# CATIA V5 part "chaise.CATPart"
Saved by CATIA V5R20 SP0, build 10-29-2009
Part number: chese
Bounding box of the stored display mesh (mm): x -75.226 to 75.782, y -50 to 50, z -81 to 122
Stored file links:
  C:\Users\bensf\Desktop\bouthaina\chese.CATPart
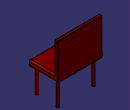
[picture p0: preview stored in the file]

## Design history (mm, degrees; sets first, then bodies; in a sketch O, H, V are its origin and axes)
Body1 (main body)
  Sketch1 on xy-plane, origin (0, 0, 0), H (1, 0, 0), V (0, 1, 0)
    line L1 (75.2257, 50) -> (75.2257, -50)
    line L2 (75.2257, -50) -> (-75.2257, -50)
    line L3 (-75.2257, -50) -> (-75.2257, 50)
    line L4 (-75.2257, 50) -> (75.2257, 50)
    length L3 = 100
    vertical: L1 V, L3 V
    horizontal: L2 H, L4 H
    equidistance: L1 L3 O, L2 L4 O
  Pad1: profile Sketch1, direction (0, 0, 1), length 20
  Sketch2 on end face of Pad1, origin (0, 0, 20), H (1, 0, 0), V (0, 1, 0)
    line L1 (75.7822, 40) -> (-74.2178, 40)
    line L2 (-74.2178, 40) -> (-74.2178, 50)
    line L3 (-74.2178, 50) -> (75.7822, 50)
    line L4 (75.7822, 50) -> (75.7822, 40)
    length L3 = 150
    horizontal: L1 H, L3 H
    vertical: L2 V, L4 V
  Pad2: profile Sketch2, direction (0, 0, 1), length 102
  Sketch3 on start face of Pad1, origin (0, 0, 0), H (1, 0, 0), V (0, -1, 0)
    circle A1 centre (60.3966, 35.0158) radius 5
    circle A2 centre (-60.3966, 35.0158) radius 5
    circle A3 centre (60.3966, -35.0158) radius 5
    circle A4 centre (-60.3966, -35.0158) radius 5
    radius A1 = 5
    symmetry: A1 A2 V, A1 A3 H, A2 A4 H
  Pad3: profile Sketch3, direction (0, 0, -1), length 81
  Fillet1: radius 5, on edge [face of Pad1 from Sketch1.L1 | end face of Pad1]
  Fillet2: radius 5, on edge [face of Pad1 from Sketch1.L2 | end face of Pad1]
  Fillet3: radius 5, on edge [face of Pad1 from Sketch1.L3 | end face of Pad1]
  Fillet4: radius 5, on edge [start face of Pad1 | face of Pad1 from Sketch1.L2]
  Chamfer1: length 1, angle 45, on face of Pad2 from Sketch2.L1
  Chamfer2: length 1, angle 45, on face of Pad2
